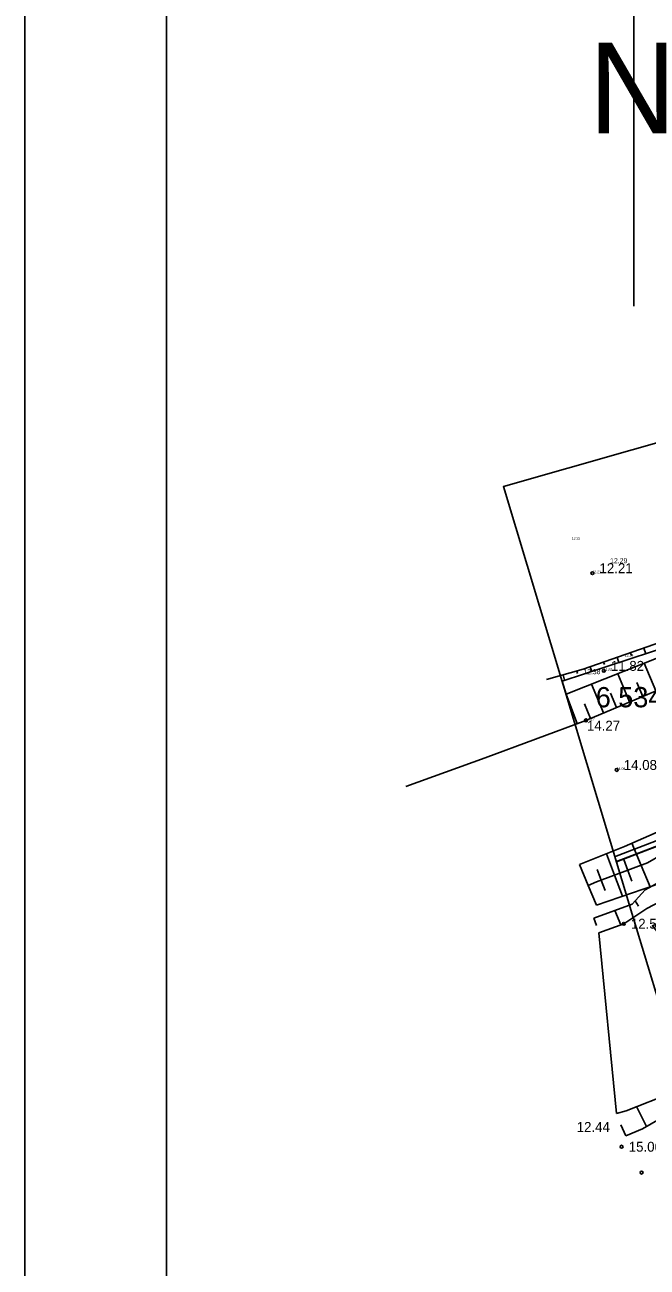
# Model space of a CAD drawing. Extents: x 433497 to 434382, y 6534486 to 6534993.
# Drawn here: x 433496.6 to 433584.4, y 6534719.6 to 6534894.8 of the extents above; entities that cross this region are included whole.
import ezdxf

# ---------------------------------------------------------------- set-up
doc = ezdxf.new("R2010")
doc.units = 0
for name, color, linetype in [('kataster', 7, 'Continuous'), ('KORGUS-EH2000', 7, 'Continuous'), ('MOOTKORG-EH2000', 7, 'Continuous'), ('PIIR', 7, 'Continuous'), ('RELJEEF', 7, 'Continuous'), ('VEEKOGU', 7, 'Continuous'), ('VORK', 7, 'Continuous'), ('VORMISTUS', 7, 'Continuous')]:
    doc.layers.add(name, color=color, linetype=linetype)

msp = doc.modelspace()

# ---------------------------------------------------------------- linework, layer by layer
at = {"layer": 'kataster'}
msp.add_lwpolyline([(433658.34, 6534546.76), (433632.77, 6534606.03), (433617.1, 6534791), (433580.11, 6534776.84)], dxfattribs=at)
at = {"layer": 'KORGUS-EH2000'}
for centre in [(433576.69, 6534817.49), (433578.3, 6534803.72), (433575.79, 6534796.74), (433580.12, 6534789.75), (433581.12, 6534768.06), (433580.82, 6534736.62), (433583.64, 6534732.97)]:
    msp.add_circle(centre, 0.2, dxfattribs=at)
at = {"layer": 'PIIR'}
for points in [[(433616.06, 6534791.42), (433579.81, 6534777.51)], [(433615.41, 6534790.32), (433580.11, 6534776.81)]]:
    msp.add_lwpolyline(points, dxfattribs=at)
at = {"layer": 'RELJEEF'}
for p, q in [((433580.17, 6534805.61), (433580.42, 6534804.89)), ((433582.19, 6534805.89), (433582.05, 6534806.27)), ((433583.94, 6534806.93), (433584.22, 6534806.13)), ((433576.39, 6534804.29), (433576.61, 6534803.64)), ((433578.4, 6534804.61), (433578.28, 6534804.95)), ((433585.64, 6534800.89), (433584, 6534804.78)), ((433572.56, 6534803.16), (433572.77, 6534802.39)), ((433574.58, 6534803.35), (433574.48, 6534803.69)), ((433581.95, 6534799.34), (433580.28, 6534803.31)), ((433582.97, 6534802.08), (433583.8, 6534800.11)), ((433574.56, 6534796.28), (433572.99, 6534800.42)), ((433578.27, 6534797.79), (433576.56, 6534801.83)), ((433579.27, 6534800.57), (433580.11, 6534798.56)), ((433575.59, 6534799.06), (433576.42, 6534797.01)), ((433583.57, 6534776.29), (433582.25, 6534779.4)), ((433579.82, 6534774.9), (433578.69, 6534777.94)), ((433576.09, 6534773.45), (433574.87, 6534776.41)), ((433581.12, 6534777.14), (433581.7, 6534775.59)), ((433583.57, 6534776.29), (433584.85, 6534773.27)), ((433577.37, 6534775.69), (433577.95, 6534774.2)), ((433578.51, 6534772.75), (433577.95, 6534774.2)), ((433579.82, 6534774.9), (433580.92, 6534771.93)), ((433582.26, 6534774.08), (433581.7, 6534775.59)), ((433576.09, 6534773.45), (433577.25, 6534770.67)), ((433583.22, 6534770.52), (433582.72, 6534771.27)), ((433583.22, 6534770.52), (433582.72, 6534771.27)), ((433577.25, 6534767.81), (433576.88, 6534768.83)), ((433577.25, 6534767.81), (433576.88, 6534768.83)), ((433579.88, 6534769.93), (433580.72, 6534767.91)), ((433579.88, 6534769.93), (433580.72, 6534767.91)), ((433584.33, 6534739.48), (433582.9, 6534742.27)), ((433580.72, 6534739.72), (433581.42, 6534738.15))]:
    msp.add_line(p, q, dxfattribs=at)
for points in [[(433749.06, 6534856.33), (433741.84, 6534853.46), (433717.91, 6534845.41), (433702.33, 6534840.51), (433691.76, 6534835.12), (433679.53, 6534829.76), (433651.53, 6534818.64), (433637.33, 6534811.85), (433630.6, 6534812.13), (433622.04, 6534814.38), (433614.68, 6534815.12), (433605.84, 6534813), (433591.43, 6534809.54), (433575.41, 6534803.95), (433570.23, 6534802.51)], [(433641.31, 6534803.13), (433635.11, 6534803.27), (433622.18, 6534806.73), (433614.95, 6534807.75), (433613.94, 6534808.88), (433598.51, 6534805.62), (433588.39, 6534802.04), (433575.79, 6534796.74), (433561.57, 6534791.45), (433550.39, 6534787.43)], [(433607.53, 6534783.68), (433607.46, 6534785.38), (433604.4, 6534786.3), (433602.96, 6534785.85), (433601.11, 6534787.26), (433594.61, 6534784.81), (433581.23, 6534778.95), (433574.87, 6534776.41)], [(433605.59, 6534784.71), (433602.85, 6534784.31), (433600.84, 6534784.55), (433595.76, 6534781.83), (433592.36, 6534780.75), (433588.68, 6534779.08), (433584.48, 6534776.63), (433577.27, 6534773.95), (433576.09, 6534773.45)], [(433609.4, 6534755.13), (433610.55, 6534754.4), (433613.7, 6534756.4), (433615.74, 6534759.33), (433617.23, 6534762.85), (433616.48, 6534763.78), (433618.17, 6534769.63), (433619.03, 6534774.03), (433619.71, 6534774.42), (433619.69, 6534777.91), (433619.14, 6534781.11), (433617.96, 6534783.31), (433615.02, 6534785.17), (433613.41, 6534785.48), (433609.97, 6534784.53), (433605.43, 6534781.62), (433601.38, 6534780.25), (433599.68, 6534780.06), (433594.48, 6534777.88), (433589.45, 6534775.75), (433584.16, 6534772.86), (433582.31, 6534770.82), (433576.88, 6534768.83)], [(433577.25, 6534770.67), (433585.49, 6534773.5), (433590.87, 6534777.19), (433593.44, 6534778.25), (433597.8, 6534779.09), (433601.57, 6534782.1), (433603.83, 6534783.19), (433607.53, 6534783.68)], [(433581.42, 6534738.15), (433583.78, 6534739.16), (433587.75, 6534741.43), (433589.3, 6534741.01), (433595.25, 6534736.02), (433596.63, 6534735.26)]]:
    msp.add_lwpolyline(points, dxfattribs=at)
at = {"layer": 'VEEKOGU'}
for p, q in [((433572.41, 6534802.27), (433572.97, 6534800.41)), ((433577.59, 6534766.8), (433580.1, 6534741.31)), ((433580.1, 6534741.31), (433581.45, 6534741.7))]:
    msp.add_line(p, q, dxfattribs=at)
for points in [[(433749.06, 6534856.33), (433741.84, 6534853.46), (433722.77, 6534845.25), (433710.51, 6534841.2), (433704.41, 6534838.97), (433698.91, 6534836.04), (433689.96, 6534831.85), (433681.03, 6534828.64), (433674.29, 6534826.03), (433651.65, 6534816.53), (433637.53, 6534810.18), (433630.8, 6534811.07), (433623.41, 6534812.9), (433613.31, 6534813.67), (433591.34, 6534808.45), (433572.41, 6534802.27)], [(433572.97, 6534800.41), (433591.85, 6534807.89), (433613.84, 6534811.69), (433622.81, 6534811.64), (433631.73, 6534808.6), (433638.35, 6534808.16), (433643.54, 6534810.24), (433652.76, 6534814.83), (433676.02, 6534824.84), (433679.31, 6534824.21), (433682.46, 6534827.26), (433690.57, 6534830.59), (433710.13, 6534839.08), (433723.05, 6534843.92), (433736.06, 6534848.41), (433747.79, 6534853.33), (433748.77, 6534853.28)], [(433581.45, 6534741.7), (433587.88, 6534744.23), (433592.47, 6534744.94), (433596.34, 6534751.6), (433596.92, 6534753.87), (433595.63, 6534755.65), (433591.98, 6534758.29), (433590.37, 6534761.42), (433585.16, 6534767.78), (433588.09, 6534769.06), (433591.89, 6534770.47), (433592.25, 6534772.22), (433592.17, 6534774.75), (433589.59, 6534772.94), (433584.36, 6534770.2), (433581.12, 6534768.06), (433577.59, 6534766.8)]]:
    msp.add_lwpolyline(points, dxfattribs=at)
at = {"layer": 'VORMISTUS'}
msp.add_line((433582.56, 6534855.14), (433582.52, 6534926.38), dxfattribs=at)
for points in [[(433496.62, 6534983.07), (433496.62, 6534486.03), (434381.62, 6534486.03), (434381.62, 6534983.07)], [(434376.62, 6534978.07), (433516.62, 6534978.07), (433516.62, 6534491.03), (434376.62, 6534491.03)]]:
    msp.add_lwpolyline(points, close=True, dxfattribs=at)
msp.add_lwpolyline([(433756.83, 6534894.35), (433691.2, 6534872.09), (433653.51, 6534864.19), (433636.55, 6534862.39), (433627.67, 6534847.82), (433564.13, 6534829.69), (433582.61, 6534768.48), (433587.88, 6534751), (433591.76, 6534747.47), (433594.1, 6534737.42), (433589.97, 6534732.12), (433592.57, 6534706.45), (433596.13, 6534671.3), (433599.93, 6534613.56), (433630.45, 6534534.94), (433664.15, 6534549.23), (433704.54, 6534572.57), (433752.08, 6534596.22), (433789.5, 6534614.84)], dxfattribs=at)
msp.add_lwpolyline([(433756.83, 6534894.35), (433691.2, 6534872.09), (433653.51, 6534864.19), (433636.55, 6534862.39), (433627.67, 6534847.82), (433564.13, 6534829.69), (433582.61, 6534768.48), (433587.88, 6534751), (433591.76, 6534747.47), (433594.1, 6534737.42), (433589.97, 6534732.12), (433592.57, 6534706.45), (433596.13, 6534671.3), (433599.93, 6534613.56), (433630.45, 6534534.94), (433664.15, 6534549.23), (433704.54, 6534572.57), (433752.08, 6534596.22), (433789.5, 6534614.84)], dxfattribs=at)

# ---------------------------------------------------------------- texts
at = {"layer": 'KORGUS-EH2000'}
for s, p in [('12.21', (433577.69, 6534817.49)), ('11.82', (433579.3, 6534803.72)), ('14.27', (433575.92, 6534795.29)), ('14.08', (433581.12, 6534789.75)), ('12.52', (433582.12, 6534767.36)), ('12.44', (433574.48, 6534738.71)), ('15.06', (433581.82, 6534735.92))]:
    msp.add_text(s, height=1.4, dxfattribs=at).set_placement(p)
at = {"layer": 'MOOTKORG-EH2000'}
for s, height, p in [('12.32', 0.35, (433573.78, 6534822.21)), ('12.29', 0.7, (433579.2, 6534818.9)), ('12.29', 0.7, (433579.2, 6534818.9)), ('12.21', 0.35, (433576.69, 6534817.49)), ('12.34', 0.35, (433581.28, 6534805.74)), ('12.38', 0.7, (433575.41, 6534803.25)), ('11.82', 0.35, (433578.3, 6534803.72)), ('14.27', 0.35, (433575.79, 6534796.74)), ('14.08', 0.35, (433580.12, 6534789.75))]:
    msp.add_text(s, height=height, dxfattribs=at).set_placement(p)
at = {"layer": 'VORK'}
msp.add_text('6 534 800 ', height=2.85, dxfattribs=at).set_placement((433577.17, 6534798.58))
at = {"layer": 'VORMISTUS'}
msp.add_text('N', height=12.76, dxfattribs=at).set_placement((433576.2, 6534879.53))

doc.saveas('drawing.dxf')
